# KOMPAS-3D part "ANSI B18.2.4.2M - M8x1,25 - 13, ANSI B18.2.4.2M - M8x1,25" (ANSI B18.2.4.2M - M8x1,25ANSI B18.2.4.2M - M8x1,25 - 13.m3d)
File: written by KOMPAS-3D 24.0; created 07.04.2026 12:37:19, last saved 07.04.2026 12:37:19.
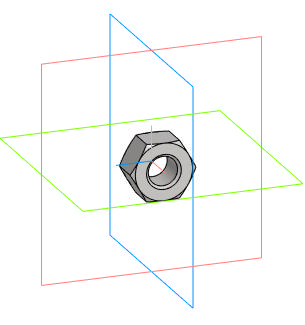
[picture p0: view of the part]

Document properties: Автор: Main; Полное имя файла: D:\DN.ru Аутсерс\Стекло смотровое DN.ru\Исходники\Стекло смотровое DN.ru SG2-34G-F тип В ГОСТ 21836-2021 Ду100 Ру16, углеродистая сталь, фланцевое\ANSI B18.2.4.2M - M8x1,25ANSI B18.2.4.2M - M8x1,25 - 13.m3d

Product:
- Body: Solid1  | qty 1
- Part/product: ANSI B18.2.4.2M - M8x1,25 - 13  | designation ANSI B18.2.4.2M - M8x1,25
    Комментарий: Типы метрических   шестигранных гаек   2
    additional columns: Сталь, мягкая

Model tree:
1. Solid1  (labels: Solid1)

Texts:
  ANSI B18.2.4.2M - M8x1,25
